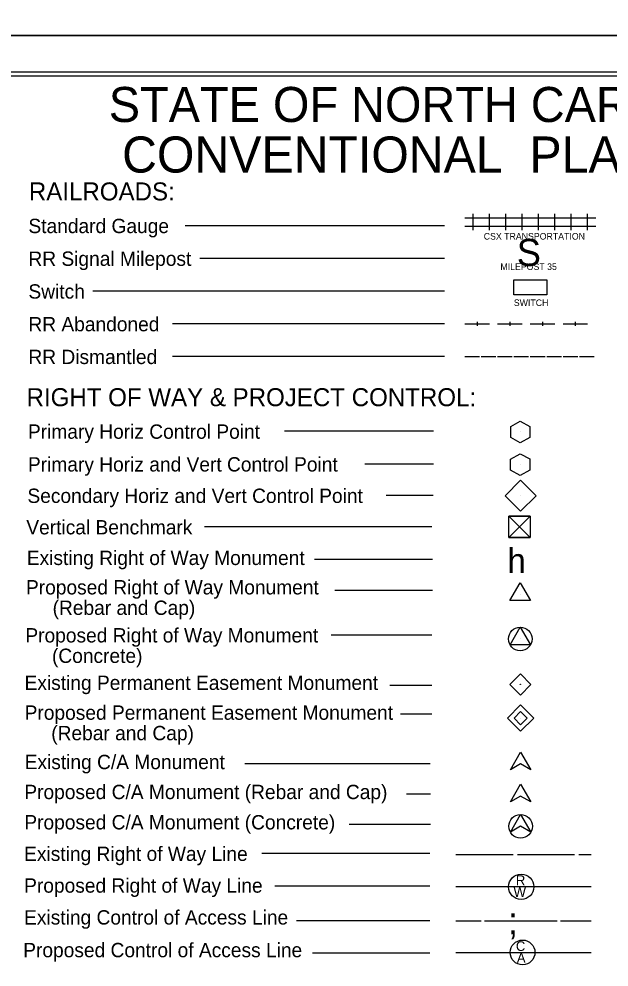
# Model space of a CAD drawing. Extents: x 925297 to 940193, y 663541 to 689899.
# Drawn here: x 929797 to 932679, y 667786 to 672419 of the extents above; entities that cross this region are included whole.
import ezdxf

# ---------------------------------------------------------------- set-up
doc = ezdxf.new("R2010")
doc.units = 0
for name, color, linetype in [('Default', 7, 'Continuous'), ('Sheet Cutting Line CELL', 7, 'Continuous'), ('Sheet Plot Border Inside CELL', 7, 'Continuous'), ('Sheet Plot Border Outside CELL', 7, 'Continuous'), ('Sheet Symbology CELL', 7, 'Continuous')]:
    doc.layers.add(name, color=color, linetype=linetype)

msp = doc.modelspace()

# ---------------------------------------------------------------- linework, layer by layer
at = {"layer": 'Default'}
for p, q in [((932245.6, 670400.9), (932245.6, 670400.9)), ((932245.5, 670241.2), (932245.5, 670241.2)), ((932246.6, 670088.6), (932246.6, 670088.6)), ((932242.6, 669936.7), (932242.6, 669936.7)), ((932246.3, 669167.2), (932246.3, 669167.2)), ((932247.7, 669002.4), (932247.7, 669002.4))]:
    msp.add_line(p, q, dxfattribs=at)
for points in [[(932245.6, 670347.7), (932199.2, 670374), (932199.2, 670427.2), (932245.6, 670454.1), (932291.9, 670427.8), (932291.9, 670374), (932245.6, 670347.7)], [(932294.4, 669988.5), (932190.6, 669884.7), (932242.5, 669936.6), (932294.4, 669884.7), (932190.6, 669988.5)], [(932242.5, 669936.6), (932294.4, 669988.5), (932190.6, 669988.5), (932242.5, 669936.6)], [(932242.5, 669936.6), (932190.6, 669884.7), (932294.4, 669884.7), (932242.5, 669936.6)]]:
    msp.add_lwpolyline(points, dxfattribs=at)
for points in [[(932198.9, 670268.2), (932245.8, 670294.3), (932292.7, 670268.6), (932291.9, 670214.8), (932245, 670187.6), (932198.9, 670213.7)], [(932171.3, 670088.9), (932247, 670164.5), (932322.7, 670088.8), (932247.1, 670013.1)], [(932190.6, 669988.5), (932294.4, 669988.5), (932294.4, 669884.7), (932190.6, 669884.7)], [(932194.3, 669167.2), (932246.3, 669219.1), (932298.2, 669167.2), (932246.3, 669115.2)], [(932247.7, 669066.7), (932312.1, 669002.3), (932247.7, 668938), (932183.3, 669002.3)], [(932247.7, 669034.5), (932279.9, 669002.3), (932247.7, 668970.1), (932215.5, 669002.3)]]:
    msp.add_lwpolyline(points, close=True, dxfattribs=at)
msp.add_circle((932246.3, 669167.2), 1.01, dxfattribs=at)
at = {"layer": 'Sheet Cutting Line CELL'}
msp.add_line((938764.7, 672338.7), (925296.7, 672338.7), dxfattribs=at)
at = {"layer": 'Sheet Plot Border Inside CELL'}
msp.add_lwpolyline([(925400.7, 663720.9), (938728.7, 663720.9), (938728.7, 672159.2), (925400.7, 672159.2)], close=True, dxfattribs=at)
at = {"layer": 'Sheet Plot Border Outside CELL'}
for points in [[(925296.7, 672338.7), (938764.7, 672338.7), (938764.7, 681098.7), (925296.7, 681098.7)], [(925296.7, 663541.3), (938764.7, 663541.3), (938764.7, 672338.7), (925296.7, 672338.7)]]:
    msp.add_lwpolyline(points, close=True, dxfattribs=at)
at = {"layer": 'Sheet Symbology CELL'}
for p, q in [((931974.9, 671446.6), (932054.9, 671446.6)), ((932014.9, 671386.6), (932014.9, 671466.6)), ((932054.9, 671446.6), (932134.8, 671446.6)), ((932094.8, 671386.6), (932094.8, 671466.6)), ((932134.8, 671446.6), (932214.8, 671446.6)), ((932174.8, 671386.6), (932174.8, 671466.6)), ((932214.8, 671446.6), (932294.8, 671446.6)), ((932254.8, 671386.6), (932254.8, 671466.6)), ((932294.8, 671446.6), (932374.8, 671446.6)), ((932334.8, 671386.6), (932334.8, 671466.6)), ((932374.8, 671446.6), (932454.7, 671446.6)), ((932414.7, 671386.6), (932414.7, 671466.6)), ((932454.7, 671446.6), (932534.7, 671446.6)), ((932494.7, 671386.6), (932494.7, 671466.6)), ((932534.7, 671446.6), (932614.7, 671446.6)), ((932574.7, 671386.6), (932574.7, 671466.6)), ((931875.8, 671408.5), (930608.8, 671408.5)), ((931974.9, 671406.6), (932054.9, 671406.6)), ((932054.9, 671406.6), (932134.8, 671406.6)), ((932134.8, 671406.6), (932214.8, 671406.6)), ((932214.8, 671406.6), (932294.8, 671406.6)), ((932294.8, 671406.6), (932374.8, 671406.6)), ((932374.8, 671406.6), (932454.7, 671406.6)), ((932454.7, 671406.6), (932534.7, 671406.6)), ((932534.7, 671406.6), (932614.7, 671406.6)), ((931875.8, 671248.6), (930679.7, 671248.6)), ((931875.8, 671088.6), (930157, 671088.6)), ((932034.9, 670938.7), (932034.9, 670918.7)), ((932194.8, 670938.7), (932194.8, 670918.7)), ((932354.8, 670938.7), (932354.8, 670918.7)), ((932514.7, 670938.7), (932514.7, 670918.7)), ((931875.8, 670928.7), (930546.9, 670928.7)), ((931974.9, 670928.7), (932094.8, 670928.7)), ((932134.8, 670928.7), (932254.8, 670928.7)), ((932294.8, 670928.7), (932414.7, 670928.7)), ((932454.7, 670928.7), (932574.7, 670928.7)), ((931875.8, 670768.7), (930546.9, 670768.7)), ((931875.8, 670768.7), (930546.9, 670768.7)), ((931974.9, 670768.7), (932046.9, 670768.7)), ((932054.9, 670768.7), (932126.8, 670768.7)), ((932134.8, 670768.7), (932206.8, 670768.7)), ((932214.8, 670768.7), (932286.8, 670768.7)), ((932294.8, 670768.7), (932366.8, 670768.7)), ((932374.8, 670768.7), (932446.7, 670768.7)), ((932454.7, 670768.7), (932526.7, 670768.7)), ((932534.7, 670768.7), (932606.7, 670768.7)), ((931822.2, 670403.9), (931094.2, 670403.9)), ((931822.2, 670243.9), (931487, 670243.9)), ((931819.7, 670090.3), (931591.4, 670090.3)), ((931814.2, 669936.6), (930703.8, 669936.6)), ((931816.7, 669776.8), (931240.5, 669776.8)), ((931817.5, 669626.6), (931339.8, 669626.6)), ((932245.5, 669605.6), (932245.5, 669605.6)), ((931813.5, 669407.4), (931321.8, 669407.4)), ((932245.7, 669389.2), (932245.7, 669389.2)), ((931814.1, 669161.9), (931607.9, 669161.9)), ((931814.1, 669021), (931660, 669021)), ((932197.6, 668749.8), (932247.6, 668836.2)), ((932247.6, 668836.2), (932297.6, 668749.8)), ((931806.2, 668779.3), (930900.6, 668779.3)), ((932247.6, 668778.6), (932197.6, 668749.8)), ((932297.6, 668749.8), (932247.6, 668778.6)), ((932197.3, 668593), (932247.3, 668679.3)), ((932247.3, 668679.3), (932297.3, 668593)), ((931807, 668631.1), (931690.5, 668631.1)), ((932247.3, 668621.8), (932197.3, 668593)), ((932297.3, 668593), (932247.3, 668621.8)), ((932197.3, 668445), (932247.3, 668531.3)), ((932247.3, 668531.3), (932297.3, 668445)), ((931807, 668483.1), (931409.8, 668483.1)), ((932247.3, 668473.7), (932197.3, 668445)), ((932297.3, 668445), (932247.3, 668473.7)), ((931803.5, 668340.9), (930983.6, 668340.9)), ((931931.7, 668336.3), (932211.6, 668336.3)), ((932231.6, 668336.3), (932511.5, 668336.3)), ((932531.5, 668336.3), (932591.5, 668336.3)), ((931803.5, 668180.9), (931047.5, 668180.9)), ((931931.7, 668179.9), (932591.5, 668179.9)), ((931803.5, 668012), (931153.1, 668012)), ((931931.7, 668012), (932055.3, 668012)), ((932071.3, 668012), (932426.5, 668012)), ((932442.5, 668012), (932591.5, 668012)), ((931803.5, 667853.5), (931230.5, 667853.5)), ((931931.7, 667856.5), (932591.5, 667856.5))]:
    msp.add_line(p, q, dxfattribs=at)
for points in [[(938628.7, 672138.8), (926632.3, 672138.8), (926632.3, 663749.4), (938628.7, 663749.4)], [(932214.8, 671144.3), (932374.8, 671144.3), (932374.8, 671071.5), (932214.8, 671071.5)], [(932195.6, 669576.8), (932245.5, 669663.2), (932295.5, 669576.8)], [(932195.7, 669360.4), (932245.7, 669446.8), (932295.7, 669360.4)]]:
    msp.add_lwpolyline(points, close=True, dxfattribs=at)
for centre, radius in [((932245.7, 669389.2), 57.6), ((932247.3, 668473.7), 57.6), ((932250.4, 668178.3), 62), ((932256.8, 667857.4), 60.6)]:
    msp.add_circle(centre, radius, dxfattribs=at)

# ---------------------------------------------------------------- texts
for s, height, p in [('STATE OF NORTH CAROLINA, DIVISION OF HIGHWAYS', 171.301, (930235.7, 671915.2)), ('CONVENTIONAL  PLAN SHEET SYMBOLS', 176.206, (930300.7, 671668.2)), ('RAILROADS:', 87.97, (929845.3, 671532.1)), ('Standard Gauge', 69.979, (929843.1, 671372.3)), ('S', 132, (932228.9, 671211.6)), ('RR Signal Milepost', 69.979, (929843.1, 671212.4)), ('Switch', 69.98, (929843.1, 671052.4)), ('RR Abandoned', 69.979, (929843.1, 670892.5)), ('RR Dismantled', 69.979, (929843.1, 670732.5)), ('RIGHT OF WAY & PROJECT CONTROL:', 87.974, (929834, 670526.6)), ('Primary Horiz Control Point', 69.979, (929840.8, 670367.5)), ('Primary Horiz and Vert Control Point', 69.979, (929840.8, 670207.5)), ('Secondary Horiz and Vert Control Point', 69.979, (929838.3, 670053.9)), ('Vertical Benchmark', 69.979, (929832.8, 669900.2)), ('Existing Right of Way Monument', 69.979, (929835.3, 669750.5)), ('h', 120, (932183.4, 669711.4)), ('Proposed Right of Way Monument', 69.979, (929831.2, 669606.8)), ('     (Rebar and Cap)', 69.979, (929831.2, 669506.8)), ('Proposed Right of Way Monument', 69.979, (929828.2, 669372.1)), ('     (Concrete)', 69.979, (929828.2, 669272.1)), ('Existing Permanent Easement Monument', 69.979, (929824.3, 669140.2)), ('Proposed Permanent Easement Monument', 69.979, (929824.6, 668994.4)), ('     (Rebar and Cap)', 69.979, (929824.6, 668894.4)), ('Existing C/A Monument', 69.979, (929824.8, 668753.1)), ('Proposed C/A Monument (Rebar and Cap)', 69.979, (929823.1, 668606.7)), ('Proposed C/A Monument (Concrete)', 69.979, (929823.1, 668458.7)), ('Existing Right of Way Line', 69.979, (929822.1, 668304.5)), ('Proposed Right of Way Line', 69.979, (929822.1, 668149.5)), ('R', 48.6, (932223.7, 668185.6)), ('W', 48.6, (932212.7, 668128.4)), ('Existing Control of Access Line', 69.979, (929822.1, 667993.9)), (';', 132, (932186, 667946.5)), ('Proposed Control of Access Line', 69.979, (929817.7, 667834.1)), ('C', 47.5, (932224.5, 667864.5)), ('A', 47.5, (932229.3, 667807.5))]:
    msp.add_text(s, height=height, dxfattribs=at).set_placement(p)
for s, p in [('CSX TRANSPORTATION', (932067.4, 671340.7)), ('MILEPOST 35', (932148.8, 671192.2)), ('SWITCH', (932214.4, 671016.2))]:
    msp.add_text(s, height=31.99, rotation=360, dxfattribs=at).set_placement(p)

doc.saveas('drawing.dxf')
